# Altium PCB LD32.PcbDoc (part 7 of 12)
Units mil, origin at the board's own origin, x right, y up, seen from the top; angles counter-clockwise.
Board outline 7007.87 x 4368.85 mil, 12 copper layers (Top Layer, Int1 (GND), Int2 (AVDD), Int3 (DVDD), Int4 (GND), Int5 (ST), Int6 (SB), Int8 (AGND), Int7 (AVCC), Int9 (VCCA), Int10 (GND), Bottom Layer), stack 60.136 mil thick; 1165 components, 667 nets, 3910 pads, 2570 vias.
Unrouted connection lines stored in the file: 14.
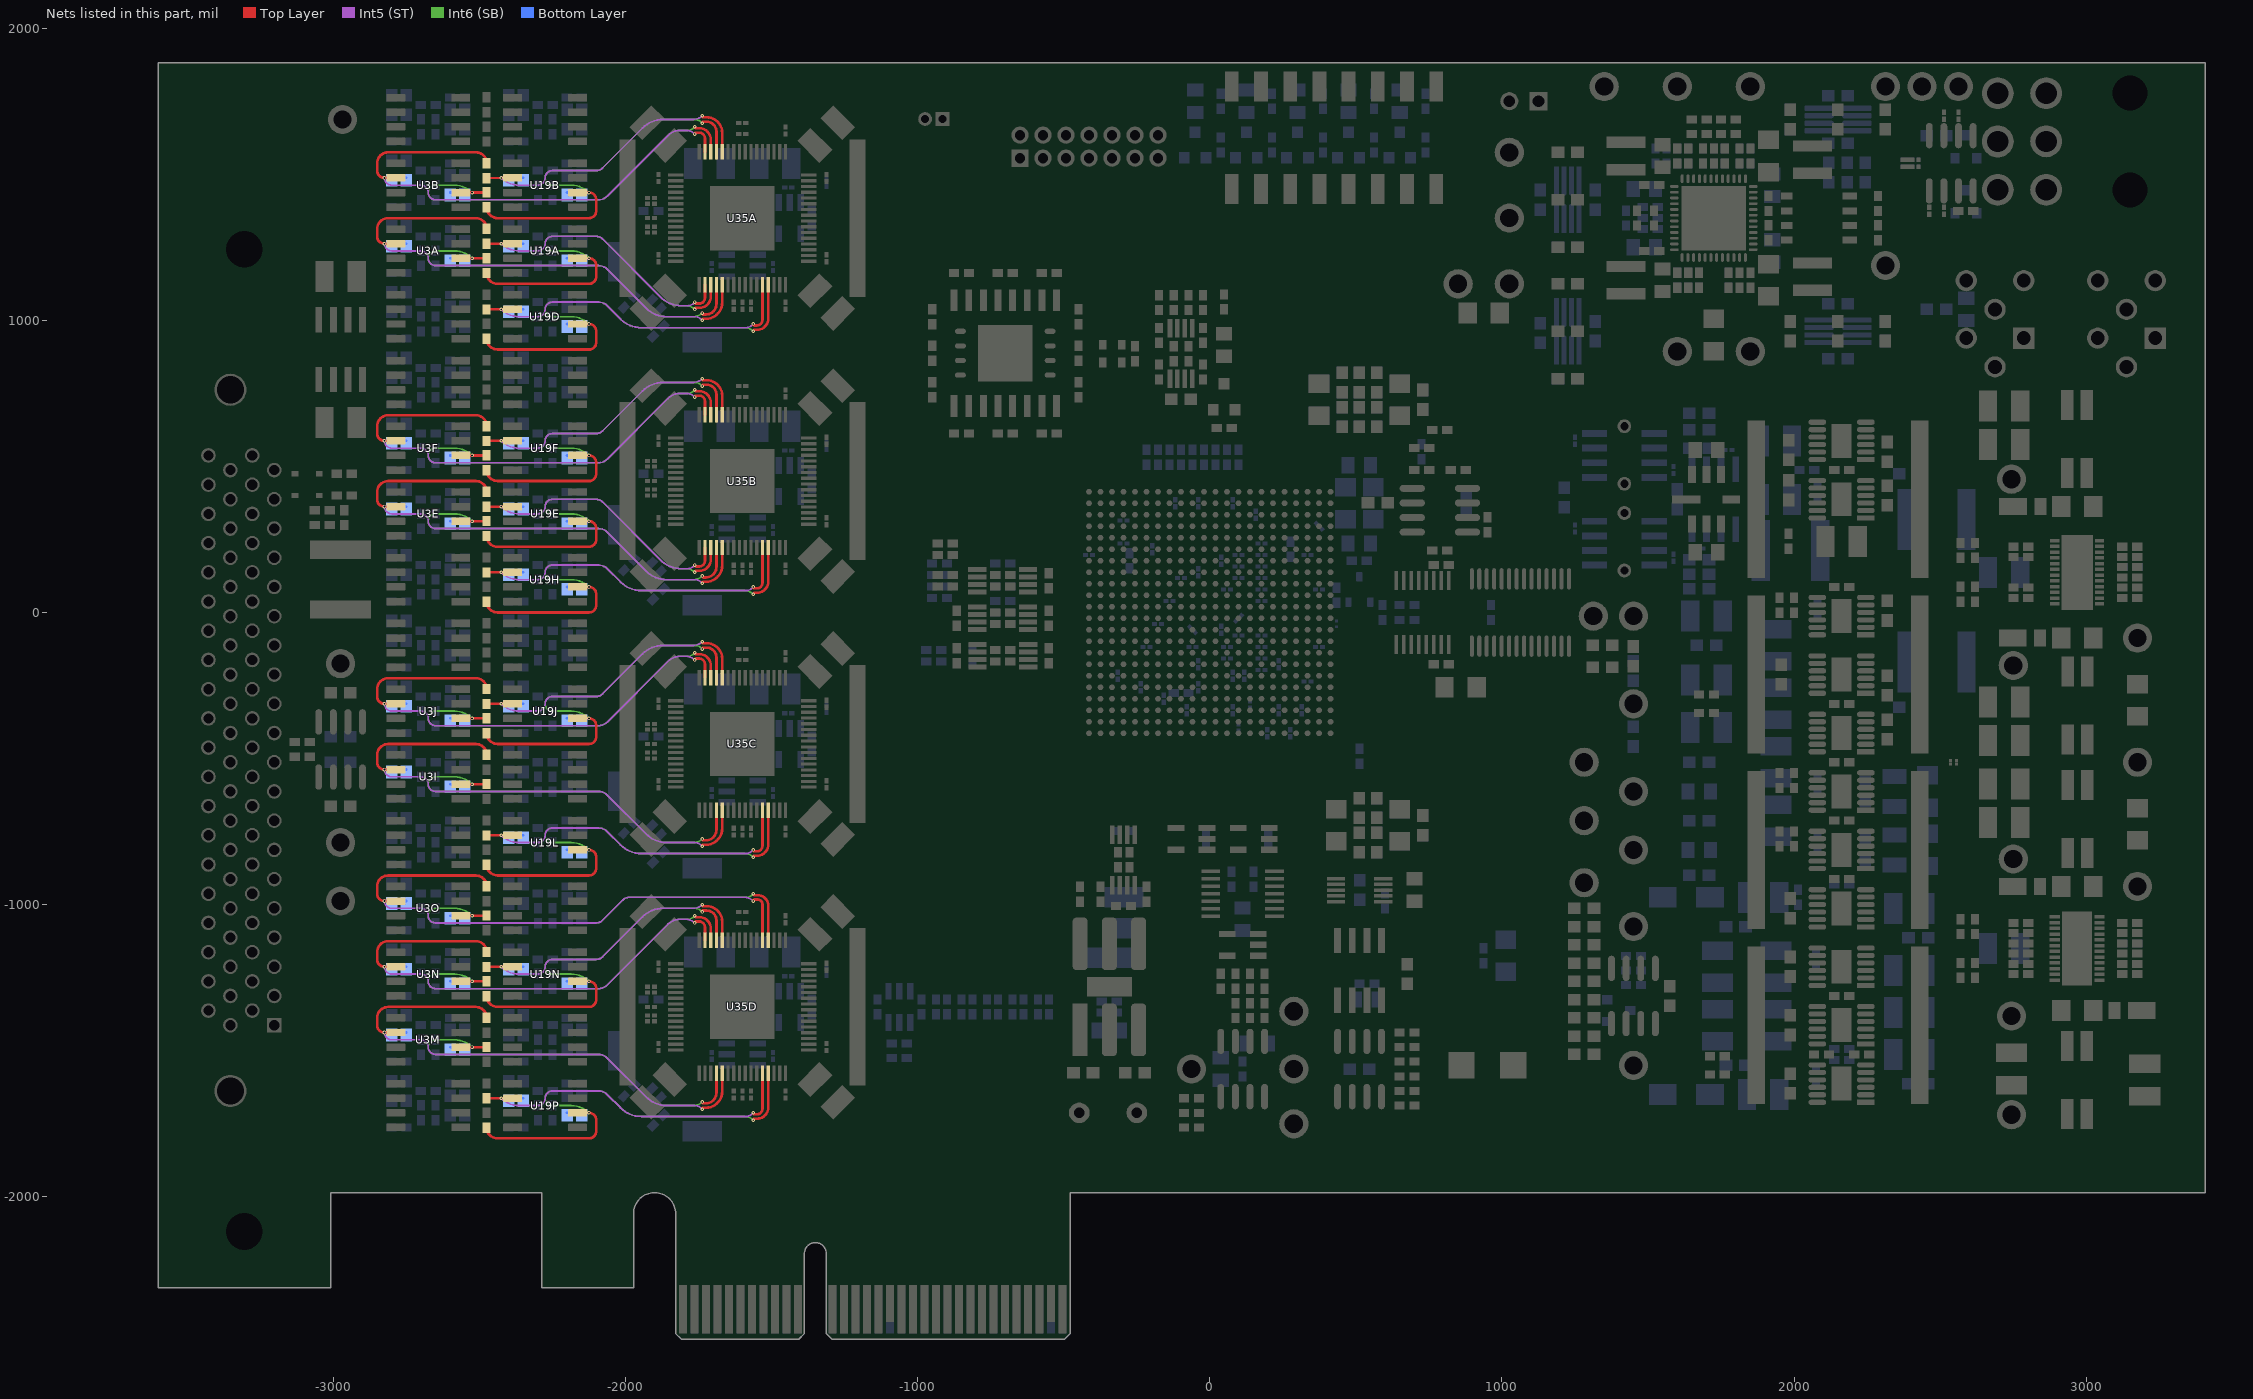
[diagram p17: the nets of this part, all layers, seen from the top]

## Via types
v1: diameter 12, hole 6, Top Layer to Bottom Layer, tented both sides, 1500 vias
v2: diameter 19, hole 10, Top Layer to Bottom Layer, tented both sides, 404 vias
v3: diameter 20, hole 10, Top Layer to Bottom Layer, tented both sides, 337 vias
v4: diameter 14, hole 7, Top Layer to Bottom Layer, tented both sides, 212 vias
v5: diameter 30, hole 15, Top Layer to Bottom Layer, tented both sides, 37 vias
v6: diameter 19.68, hole 7.87, Top Layer to Bottom Layer, 25 vias
v7: diameter 40, hole 20, Top Layer to Bottom Layer, tented both sides, 16 vias
v8: diameter 19.02, hole 10, Top Layer to Bottom Layer, tented both sides, 10 vias
v9: diameter 40, hole 20, Top Layer to Bottom Layer, 9 vias
v10: diameter 60, hole 40, Top Layer to Bottom Layer, 5 vias
v11: diameter 25, hole 13, Top Layer to Bottom Layer, 4 vias
v12: diameter 50, hole 25, Top Layer to Bottom Layer, tented both sides, 4 vias
v13: diameter 35, hole 20, Top Layer to Bottom Layer, 2 vias
v14: diameter 50, hole 25, Top Layer to Bottom Layer, 2 vias
v15: diameter 63, hole 45, Top Layer to Bottom Layer, 1 vias
v16: diameter 14.02, hole 7.01, Top Layer to Bottom Layer, tented both sides, 1 vias
v17: diameter 60, hole 40, Top Layer to Bottom Layer, tented both sides, 1 vias

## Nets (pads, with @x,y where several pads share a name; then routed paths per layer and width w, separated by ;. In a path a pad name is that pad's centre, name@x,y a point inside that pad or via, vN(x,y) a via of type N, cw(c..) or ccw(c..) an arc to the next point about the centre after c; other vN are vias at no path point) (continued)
D3D_N: C399O.2 R7O.1 R399O.1 U3O.6 U35D.4 | length 4442.7
  Top Layer w9: U3O.6@-2563.78,-1037.5 v1(-2525,-1037.5) -2475.59,-1037.5 R7O.1@-2475,-1036.91 ; v1(-1562.5,-962.5) ccw(c-1557.5,-962.5) -1557.5,-967.5 -1547.5,-967.5 cw(c-1547.5,-1003.58) -1511.42,-1003.58 U35D.4@-1511.42,-1122.5
  Int6 (SB) w6: v1(-2525,-1037.5) ccw(c-2585.36,-1097.86) -2585.36,-1012.5 -2650,-1012.5 ccw(c-2650,-1037.5) -2675,-1037.5 ccw(c-2650,-1037.5) -2650,-1062.5 ; v1@-1562.86,-962.25 cw(c-1587.5,-944.82) -1587.5,-975 -1987.5,-975 ccw(c-1987.5,-1005.18) -2008.84,-983.84 -2078.66,-1053.66 cw(c-2100,-1032.32) -2100,-1062.5 ; -2650,-1062.5 -2100,-1062.5 ; -2650,-1062.5 -2100,-1062.5 ; -2650,-1062.5 -2100,-1062.5 ; -2650,-1062.5 -2100,-1062.5 ; -2650,-1062.5 -2100,-1062.5 ; -2650,-1062.5 -2100,-1062.5
  Bottom Layer w9: R399O.1@-2600,-1037.5 v1(-2525,-1037.5)
D3D_P: C463O.2 R8O.1 R447O.1 U3O.2 U35D.5 | length 2887.1
  Top Layer w9: U3O.2@-2786.22,-987.5 v1(-2825,-987.5) cw(c-2825,-962.5) -2850,-962.5 -2850,-937.5 cw(c-2812.5,-937.5) -2812.5,-900 -2511.91,-900 ; v1(-1562.5,-987.5) cw(c-1557.5,-987.5) -1557.5,-982.5 -1547.5,-982.5 cw(c-1547.5,-998.9) -1531.1,-998.9 U35D.5@-1531.1,-1122.5 ; -2511.91,-900 cw(c-2511.91,-936.91) R8O.1@-2475,-936.91 ; -2511.91,-900 cw(c-2511.91,-936.91) R8O.1@-2475,-936.91 ; -2511.91,-900 cw(c-2511.91,-936.91) R8O.1@-2475,-936.91 ; -2511.91,-900 cw(c-2511.91,-936.91) R8O.1@-2475,-936.91 ; -2511.91,-900 cw(c-2511.91,-936.91) R8O.1@-2475,-936.91
  Int5 (ST) w6: v1(-2825,-987.5) ccw(c-2800,-987.5) -2800,-1012.5 -2700,-1012.5 cw(c-2700,-1037.5) -2675,-1037.5 ccw(c-2650,-1037.5) -2650,-1062.5 ; v1(-1562.5,-987.5) ccw(c-1592.68,-1017.68) -1592.5,-975 ; -2650,-1062.5 -2100,-1062.5 ; -2650,-1062.5 -2100,-1062.5 ; -2100,-1062.5 ccw(c-2100,-1032.32) -2078.66,-1053.66 -2008.84,-983.84 cw(c-1987.5,-1005.18) -1987.5,-975 -1592.68,-975 ; -1592.68,-975 cw(c-1592.68,-1017.68) -1592.5,-975 ; -1592.68,-975 -1592.5,-975
  Bottom Layer w9: v1(-2825,-987.5) R447O.1@-2750,-987.5
D4A_N: C319D.2 R7D.2 R335D.1 U19D.6 U35A.45 | length 2545.6
  Top Layer w9: U19D.6@-2163.78,987.5 v1(-2125,987.5) ; v1(-1562.5,962.5) cw(c-1557.5,962.5) -1557.5,967.5 -1550,967.5 ccw(c-1550,1006.08) -1511.42,1006.08 U35A.45@-1511.42,1122.5 ; R7D.2@-2475,936.91 ccw(c-2438.09,936.91) -2438.09,900 ; R7D.2@-2475,936.91 ccw(c-2438.09,936.91) -2438.09,900 ; R7D.2@-2475,936.91 ccw(c-2438.09,936.91) -2438.09,900 ; R7D.2@-2475,936.91 ccw(c-2438.09,936.91) -2438.09,900 ; R7D.2@-2475,936.91 ccw(c-2438.09,936.91) -2438.09,900 ; -2438.09,900 -2125,900 ; -2125,900 ccw(c-2125,925) -2100,925 ; -2125,900 ccw(c-2125,925) -2100,925 ; -2125,900 ccw(c-2125,925) -2100,925 ; -2125,900 ccw(c-2125,925) -2100,925 ; -2125,900 ccw(c-2125,925) -2100,925 ; -2125,900 ccw(c-2125,925) -2100,925 ; -2125,900 ccw(c-2125,925) -2100,925 ; -2125,900 ccw(c-2125,925) -2100,925 ; -2125,900 ccw(c-2125,925) -2100,925 ; -2125,900 ccw(c-2125,925) -2100,925 ; -2125,900 ccw(c-2125,925) -2100,925 ; v1(-2125,987.5) cw(c-2125,962.5) -2100,962.5 ; v1(-2125,987.5) cw(c-2125,962.5) -2100,962.5 ; v1(-2125,987.5) cw(c-2125,962.5) -2100,962.5 ; v1(-2125,987.5) cw(c-2125,962.5) -2100,962.5 ; v1(-2125,987.5) cw(c-2125,962.5) -2100,962.5 ; v1(-2125,987.5) cw(c-2125,962.5) -2100,962.5 ; -2100,925 -2100,962.5
  Int6 (SB) w6: v1(-2125,987.5) ccw(c-2185.36,927.14) -2185.36,1012.5 -2250,1012.5 cw(c-2250,1037.5) -2250,1062.5 -2092.68,1062.5 cw(c-2092.68,1019.82) -2062.5,1050 -2016.79,1004.29 ccw(c-1946.08,1075) -1946.08,975 -1592.68,975 ; v1(-1562.5,962.5) ccw(c-1592.68,932.32) -1592.5,975 ; -1592.68,975 cw(c-1592.68,932.32) -1592.5,975 ; -1592.68,975 -1592.5,975
  Bottom Layer w9: R335D.1@-2200,987.5 v1(-2125,987.5)
D4A_P: C383D.2 R8D.2 R383D.1 U19D.2 U35A.44 | length 1582.5
  Top Layer w9: R8D.2@-2475,1036.91 v1(-2425,1037.5) U19D.2@-2386.22,1037.5 U19D.2@-2380,1037.5 ; v1(-1562.5,987.5) ccw(c-1557.5,987.5) -1557.5,982.5 -1550,982.5 ccw(c-1550,1001.4) -1531.1,1001.4 U35A.44@-1531.1,1122.5
  Int5 (ST) w6: v1(-2425,1037.5) ccw(c-2364.64,1097.86) -2364.64,1012.5 -2300,1012.5 ccw(c-2300,1037.5) -2275,1037.5 cw(c-2250,1037.5) -2250,1062.5 ; v1(-1562.5,987.5) -1566.16,983.84 cw(c-1587.5,1005.18) -1587.5,975 -1946.08,975 cw(c-1946.08,1075) -2016.79,1004.29 -2062.5,1050 ccw(c-2092.68,1019.82) -2092.68,1062.5 ; -2250,1062.5 -2092.68,1062.5 ; -2250,1062.5 -2092.68,1062.5 ; -2250,1062.5 -2092.68,1062.5
  Bottom Layer w9: v1(-2425,1037.5) R383D.1@-2350,1037.5
D4B_N: C319H.2 R7H.2 R335H.1 U19H.6 U35B.45 | length 3370.5
  Top Layer w9: U19H.6@-2163.78,87.5 v1(-2125,87.5) ; -2100,25.08 cw(c-2125.08,25.08) -2125.08,0 -2438.09,0 ; v1(-1562.5,62.5) cw(c-1557.5,62.5) -1557.5,67.5 -1550,67.5 ccw(c-1550,106.08) -1511.42,106.08 U35B.45@-1511.42,222.5 ; R7H.2@-2475,36.91 ccw(c-2438.09,36.91) -2438.09,0 ; R7H.2@-2475,36.91 ccw(c-2438.09,36.91) -2438.09,0 ; R7H.2@-2475,36.91 ccw(c-2438.09,36.91) -2438.09,0 ; R7H.2@-2475,36.91 ccw(c-2438.09,36.91) -2438.09,0 ; R7H.2@-2475,36.91 ccw(c-2438.09,36.91) -2438.09,0 ; -2125,0 ccw(c-2125,25) -2100,25 ; -2125,0 ccw(c-2125,25) -2100,25 ; -2125,0 ccw(c-2125,25) -2100,25 ; -2125,0 ccw(c-2125,25) -2100,25 ; -2125,0 ccw(c-2125,25) -2100,25 ; -2125,0 ccw(c-2125,25) -2100,25 ; -2125,0 ccw(c-2125,25) -2100,25 ; -2125,0 ccw(c-2125,25) -2100,25 ; -2125,0 ccw(c-2125,25) -2100,25 ; -2125,0 ccw(c-2125,25) -2100,25 ; -2125,0 ccw(c-2125,25) -2100,25 ; -2125,0 ccw(c-2125,25) -2100,25 ; -2125,0 ccw(c-2125,25) -2100,25 ; -2125,0 ccw(c-2125,25) -2100,25 ; -2125,0 ccw(c-2125,25) -2100,25 ; -2125,0 ccw(c-2125,25) -2100,25 ; -2125,0 ccw(c-2125,25) -2100,25 ; -2125,0 ccw(c-2125,25) -2100,25 ; -2125,0 ccw(c-2125,25) -2100,25 ; -2125,0 ccw(c-2125,25) -2100,25 ; -2125,0 ccw(c-2125,25) -2100,25 ; v1(-2125,87.5) cw(c-2125,62.5) -2100,62.5 ; v1(-2125,87.5) cw(c-2125,62.5) -2100,62.5 ; v1(-2125,87.5) cw(c-2125,62.5) -2100,62.5 ; v1(-2125,87.5) cw(c-2125,62.5) -2100,62.5 ; v1(-2125,87.5) cw(c-2125,62.5) -2100,62.5 ; v1(-2125,87.5) cw(c-2125,62.5) -2100,62.5 ; v1(-2125,87.5) cw(c-2125,62.5) -2100,62.5 ; v1(-2125,87.5) cw(c-2125,62.5) -2100,62.5 ; v1(-2125,87.5) cw(c-2125,62.5) -2100,62.5 ; v1(-2125,87.5) cw(c-2125,62.5) -2100,62.5 ; v1(-2125,87.5) cw(c-2125,62.5) -2100,62.5 ; v1(-2125,87.5) cw(c-2125,62.5) -2100,62.5 ; -2100,25 -2100,62.5
  Int6 (SB) w6: v1(-2125,87.5) ccw(c-2185.36,27.14) -2185.36,112.5 -2250,112.5 cw(c-2250,137.5) -2250,162.5 ; v1(-1562.5,62.5) ccw(c-1592.68,32.32) -1592.5,75 ; -2250,162.5 -2092.68,162.5 ; -2250,162.5 -2092.68,162.5 ; -2092.68,162.5 cw(c-2092.68,119.82) -2062.5,150 -2016.79,104.29 ccw(c-1946.08,175) -1946.08,75 -1592.68,75 ; -1592.68,75 cw(c-1592.68,32.32) -1592.5,75 ; -1592.68,75 -1592.5,75
  Bottom Layer w9: R335H.1@-2200,87.5 v1(-2125,87.5)
D4B_P: C383H.2 R8H.2 R383H.1 U19H.2 U35B.44 | length 2054.5
  Top Layer w9: R8H.2@-2475,136.91 v1(-2425,137.5) U19H.2@-2386.22,137.5 U19H.2@-2380,137.5 ; v1(-1562.5,87.5) ccw(c-1557.5,87.5) -1557.5,82.5 -1550,82.5 ccw(c-1550,101.4) -1531.1,101.4 U35B.44@-1531.1,222.5
  Int5 (ST) w6: v1(-2425,137.5) ccw(c-2364.64,197.86) -2364.64,112.5 -2300,112.5 ccw(c-2300,137.5) -2275,137.5 cw(c-2250,137.5) -2250,162.5 ; v1(-1562.5,87.5) -1566.16,83.84 cw(c-1587.5,105.18) -1587.5,75 -1946.08,75 cw(c-1946.08,175) -2016.79,104.29 -2062.5,150 ccw(c-2092.68,119.82) -2092.68,162.5 ; -2250,162.5 -2092.68,162.5 ; -2250,162.5 -2092.68,162.5 ; -2250,162.5 -2092.68,162.5 ; -2250,162.5 -2092.68,162.5 ; -2250,162.5 -2092.68,162.5 ; -2250,162.5 -2092.68,162.5
  Bottom Layer w9: v1(-2425,137.5) R383H.1@-2350,137.5
D4C_N: C319L.2 R7L.2 R335L.1 U19L.6 U35C.45 | length 3370.5
  Top Layer w9: U19L.6@-2163.78,-812.5 v1(-2125,-812.5) ; -2100,-874.92 cw(c-2125.08,-874.92) -2125.08,-900 -2438.09,-900 ; v1(-1562.5,-837.5) cw(c-1557.5,-837.5) -1557.5,-832.5 -1550,-832.5 ccw(c-1550,-793.92) -1511.42,-793.92 U35C.45@-1511.42,-677.5 ; R7L.2@-2475,-863.09 ccw(c-2438.09,-863.09) -2438.09,-900 ; R7L.2@-2475,-863.09 ccw(c-2438.09,-863.09) -2438.09,-900 ; R7L.2@-2475,-863.09 ccw(c-2438.09,-863.09) -2438.09,-900 ; R7L.2@-2475,-863.09 ccw(c-2438.09,-863.09) -2438.09,-900 ; R7L.2@-2475,-863.09 ccw(c-2438.09,-863.09) -2438.09,-900 ; -2125,-900 ccw(c-2125,-875) -2100,-875 ; -2125,-900 ccw(c-2125,-875) -2100,-875 ; -2125,-900 ccw(c-2125,-875) -2100,-875 ; -2125,-900 ccw(c-2125,-875) -2100,-875 ; -2125,-900 ccw(c-2125,-875) -2100,-875 ; -2125,-900 ccw(c-2125,-875) -2100,-875 ; -2125,-900 ccw(c-2125,-875) -2100,-875 ; -2125,-900 ccw(c-2125,-875) -2100,-875 ; -2125,-900 ccw(c-2125,-875) -2100,-875 ; -2125,-900 ccw(c-2125,-875) -2100,-875 ; -2125,-900 ccw(c-2125,-875) -2100,-875 ; -2125,-900 ccw(c-2125,-875) -2100,-875 ; -2125,-900 ccw(c-2125,-875) -2100,-875 ; -2125,-900 ccw(c-2125,-875) -2100,-875 ; -2125,-900 ccw(c-2125,-875) -2100,-875 ; -2125,-900 ccw(c-2125,-875) -2100,-875 ; -2125,-900 ccw(c-2125,-875) -2100,-875 ; -2125,-900 ccw(c-2125,-875) -2100,-875 ; -2125,-900 ccw(c-2125,-875) -2100,-875 ; -2125,-900 ccw(c-2125,-875) -2100,-875 ; -2125,-900 ccw(c-2125,-875) -2100,-875 ; v1(-2125,-812.5) cw(c-2125,-837.5) -2100,-837.5 ; v1(-2125,-812.5) cw(c-2125,-837.5) -2100,-837.5 ; v1(-2125,-812.5) cw(c-2125,-837.5) -2100,-837.5 ; v1(-2125,-812.5) cw(c-2125,-837.5) -2100,-837.5 ; v1(-2125,-812.5) cw(c-2125,-837.5) -2100,-837.5 ; v1(-2125,-812.5) cw(c-2125,-837.5) -2100,-837.5 ; v1(-2125,-812.5) cw(c-2125,-837.5) -2100,-837.5 ; v1(-2125,-812.5) cw(c-2125,-837.5) -2100,-837.5 ; v1(-2125,-812.5) cw(c-2125,-837.5) -2100,-837.5 ; v1(-2125,-812.5) cw(c-2125,-837.5) -2100,-837.5 ; v1(-2125,-812.5) cw(c-2125,-837.5) -2100,-837.5 ; v1(-2125,-812.5) cw(c-2125,-837.5) -2100,-837.5 ; -2100,-875 -2100,-837.5
  Int6 (SB) w6: v1(-2125,-812.5) ccw(c-2185.36,-872.86) -2185.36,-787.5 -2250,-787.5 cw(c-2250,-762.5) -2250,-737.5 ; v1(-1562.5,-837.5) ccw(c-1592.68,-867.68) -1592.5,-825 ; -2250,-737.5 -2092.68,-737.5 ; -2250,-737.5 -2092.68,-737.5 ; -2092.68,-737.5 cw(c-2092.68,-780.18) -2062.5,-750 -2016.79,-795.71 ccw(c-1946.08,-725) -1946.08,-825 -1592.68,-825 ; -1592.68,-825 cw(c-1592.68,-867.68) -1592.5,-825 ; -1592.68,-825 -1592.5,-825
  Bottom Layer w9: R335L.1@-2200,-812.5 v1(-2125,-812.5)
D4C_P: C383L.2 R8L.2 R383L.1 U19L.2 U35C.44 | length 2054.5
  Top Layer w9: R8L.2@-2475,-763.09 v1(-2425,-762.5) U19L.2@-2386.22,-762.5 U19L.2@-2380,-762.5 ; v1(-1562.5,-812.5) ccw(c-1557.5,-812.5) -1557.5,-817.5 -1550,-817.5 ccw(c-1550,-798.6) -1531.1,-798.6 U35C.44@-1531.1,-677.5
  Int5 (ST) w6: v1(-2425,-762.5) ccw(c-2364.64,-702.14) -2364.64,-787.5 -2300,-787.5 ccw(c-2300,-762.5) -2275,-762.5 cw(c-2250,-762.5) -2250,-737.5 ; v1(-1562.5,-812.5) -1566.16,-816.16 cw(c-1587.5,-794.82) -1587.5,-825 -1946.08,-825 cw(c-1946.08,-725) -2016.79,-795.71 -2062.5,-750 ccw(c-2092.68,-780.18) -2092.68,-737.5 ; -2250,-737.5 -2092.68,-737.5 ; -2250,-737.5 -2092.68,-737.5 ; -2250,-737.5 -2092.68,-737.5 ; -2250,-737.5 -2092.68,-737.5 ; -2250,-737.5 -2092.68,-737.5 ; -2250,-737.5 -2092.68,-737.5
  Bottom Layer w9: v1(-2425,-762.5) R383L.1@-2350,-762.5
D4D_N: C319P.2 R7P.2 R335P.1 U19P.6 U35D.45 | length 2549.5
  Top Layer w9: R7P.2@-2475,-1763.09 ccw(c-2438.09,-1763.09) -2438.09,-1800 -2125,-1800 ; U19P.6@-2163.78,-1712.5 v1(-2125,-1712.5) ; v1(-1562.5,-1737.5) cw(c-1557.5,-1737.5) -1557.5,-1732.5 -1550,-1732.5 ccw(c-1550,-1693.92) -1511.42,-1693.92 U35D.45@-1511.42,-1577.5 ; -2125,-1800 ccw(c-2125,-1775) -2100,-1775 ; -2125,-1800 ccw(c-2125,-1775) -2100,-1775 ; -2125,-1800 ccw(c-2125,-1775) -2100,-1775 ; -2125,-1800 ccw(c-2125,-1775) -2100,-1775 ; -2125,-1800 ccw(c-2125,-1775) -2100,-1775 ; -2125,-1800 ccw(c-2125,-1775) -2100,-1775 ; -2125,-1800 ccw(c-2125,-1775) -2100,-1775 ; -2125,-1800 ccw(c-2125,-1775) -2100,-1775 ; -2125,-1800 ccw(c-2125,-1775) -2100,-1775 ; -2125,-1800 ccw(c-2125,-1775) -2100,-1775 ; -2125,-1800 ccw(c-2125,-1775) -2100,-1775 ; -2125,-1800 ccw(c-2125,-1775) -2100,-1775 ; v1(-2125,-1712.5) cw(c-2125,-1737.5) -2100,-1737.5 ; v1(-2125,-1712.5) cw(c-2125,-1737.5) -2100,-1737.5 ; v1(-2125,-1712.5) cw(c-2125,-1737.5) -2100,-1737.5 ; v1(-2125,-1712.5) cw(c-2125,-1737.5) -2100,-1737.5 ; v1(-2125,-1712.5) cw(c-2125,-1737.5) -2100,-1737.5 ; v1(-2125,-1712.5) cw(c-2125,-1737.5) -2100,-1737.5 ; v1(-2125,-1712.5) cw(c-2125,-1737.5) -2100,-1737.5 ; -2100,-1775 -2100,-1737.5
  Int6 (SB) w6: v1(-2125,-1712.5) ccw(c-2185.36,-1772.86) -2185.36,-1687.5 -2250,-1687.5 cw(c-2250,-1662.5) -2275,-1662.5 cw(c-2250,-1662.5) -2250,-1637.5 ; v1(-1562.5,-1737.5) ccw(c-1592.68,-1767.68) -1592.5,-1725 ; -2250,-1637.5 -2092.68,-1637.5 ; -2250,-1637.5 -2092.68,-1637.5 ; -2092.68,-1637.5 cw(c-2092.68,-1680.18) -2062.5,-1650 -2016.79,-1695.71 ccw(c-1946.08,-1625) -1946.08,-1725 -1592.68,-1725 ; -1592.68,-1725 cw(c-1592.68,-1767.68) -1592.5,-1725 ; -1592.68,-1725 -1592.5,-1725
  Bottom Layer w9: R335P.1@-2200,-1712.5 v1(-2125,-1712.5)
D4D_P: C383P.2 R8P.2 R383P.1 U19P.2 U35D.44 | length 1739.8
  Top Layer w9: R8P.2@-2475,-1663.09 v1(-2425,-1662.5) U19P.2@-2386.22,-1662.5 U19P.2@-2380,-1662.5 ; v1(-1562.5,-1712.5) ccw(c-1557.5,-1712.5) -1557.5,-1717.5 -1550,-1717.5 ccw(c-1550,-1698.6) -1531.1,-1698.6 U35D.44@-1531.1,-1577.5
  Int5 (ST) w6: v1(-2425,-1662.5) ccw(c-2364.64,-1602.14) -2364.64,-1687.5 -2300,-1687.5 ccw(c-2300,-1662.5) -2275,-1662.5 cw(c-2250,-1662.5) -2250,-1637.5 ; v1(-1562.5,-1712.5) -1566.16,-1716.16 cw(c-1587.5,-1694.82) -1587.5,-1725 -1946.08,-1725 cw(c-1946.08,-1625) -2016.79,-1695.71 -2062.5,-1650 ccw(c-2092.68,-1680.18) -2092.68,-1637.5 ; -2250,-1637.5 -2092.68,-1637.5 ; -2250,-1637.5 -2092.68,-1637.5 ; -2250,-1637.5 -2092.68,-1637.5 ; -2250,-1637.5 -2092.68,-1637.5
  Bottom Layer w9: v1(-2425,-1662.5) R383P.1@-2350,-1662.5
D5A_N: C319B.2 R7B.2 R335B.1 U19B.6 U35A.13 | length 2349.7
  Top Layer w9: U19B.6@-2163.78,1437.5 v1(-2125,1437.5) ; -2125.08,1349.86 -2438.09,1349.86 -2438.09,1350 ; v1@-1735,1680 -1722.5,1680 cw(c-1722.5,1646.08) -1688.58,1646.08 U35A.13@-1688.58,1577.5 ; R7B.2@-2475,1386.91 ccw(c-2438.09,1386.91) -2438.09,1350 ; R7B.2@-2475,1386.91 ccw(c-2438.09,1386.91) -2438.09,1350 ; R7B.2@-2475,1386.91 ccw(c-2438.09,1386.91) -2438.09,1350 ; R7B.2@-2475,1386.91 ccw(c-2438.09,1386.91) -2438.09,1350 ; R7B.2@-2475,1386.91 ccw(c-2438.09,1386.91) -2438.09,1350 ; -2125,1350 ccw(c-2125,1375) -2100,1375 ; -2125,1350 ccw(c-2125,1375) -2100,1375 ; -2125,1350 ccw(c-2125,1375) -2100,1375 ; -2125,1350 ccw(c-2125,1375) -2100,1375 ; -2125,1350 ccw(c-2125,1375) -2100,1375 ; -2125,1350 ccw(c-2125,1375) -2100,1375 ; -2125,1350 ccw(c-2125,1375) -2100,1375 ; -2125,1350 ccw(c-2125,1375) -2100,1375 ; -2125,1350 ccw(c-2125,1375) -2100,1375 ; -2125,1350 ccw(c-2125,1375) -2100,1375 ; -2125,1350 ccw(c-2125,1375) -2100,1375 ; v1(-2125,1437.5) cw(c-2125,1412.5) -2100,1412.5 ; v1(-2125,1437.5) cw(c-2125,1412.5) -2100,1412.5 ; v1(-2125,1437.5) cw(c-2125,1412.5) -2100,1412.5 ; v1(-2125,1437.5) cw(c-2125,1412.5) -2100,1412.5 ; v1(-2125,1437.5) cw(c-2125,1412.5) -2100,1412.5 ; v1(-2125,1437.5) cw(c-2125,1412.5) -2100,1412.5 ; -2100,1375 -2100,1412.5
  Int6 (SB) w6: v1(-2125,1437.5) ccw(c-2185.36,1377.14) -2185.36,1462.5 -2250,1462.5 cw(c-2250,1487.5) -2275,1487.5 cw(c-2250,1487.5) -2250,1512.5 -2100,1512.5 ccw(c-2100,1542.68) -2078.66,1521.34 -1941.79,1658.21 cw(c-1871.08,1587.5) -1871.08,1687.5 -1762.5,1687.5 cw(c-1762.5,1657.32) v1@-1737.86,1674.75
  Bottom Layer w9: R335B.1@-2200,1437.5 v1(-2125,1437.5)
  other v1: -1737.5,1675
D5A_P: C383B.2 R8B.2 R383B.1 U19B.2 U35A.12 | length 1423.7
  Top Layer w9: R8B.2@-2475,1486.91 v1(-2425,1487.5) U19B.2@-2386.22,1487.5 U19B.2@-2380,1487.5 ; v1@-1735,1695 -1722.5,1695 cw(c-1722.5,1641.4) -1668.9,1641.4 U35A.12@-1668.9,1577.5
  Int5 (ST) w6: v1(-2425,1487.5) ccw(c-2364.64,1547.86) -2364.64,1462.5 -2300,1462.5 ccw(c-2300,1487.5) -2275,1487.5 cw(c-2250,1487.5) -2250,1512.5 ; v1(-1737.5,1700) cw(c-1767.68,1730.18) -1767.5,1687.5 ; -2250,1512.5 -2100,1512.5 ; -2250,1512.5 -2100,1512.5 ; -2250,1512.5 -2100,1512.5 ; -2100,1512.5 ccw(c-2100,1542.68) -2078.66,1521.34 -1941.79,1658.21 cw(c-1871.08,1587.5) -1871.08,1687.5 -1862.5,1687.5 -1767.68,1687.5 ; -1767.68,1687.5 ccw(c-1767.68,1730.18) -1767.5,1687.5 ; -1767.68,1687.5 -1767.5,1687.5
  Bottom Layer w9: v1(-2425,1487.5) R383B.1@-2350,1487.5
D5B_N: C319F.2 R7F.2 R335F.1 U19F.6 U35B.13 | length 3167.3
  Top Layer w9: U19F.6@-2163.78,537.5 v1(-2125,537.5) ; -2100,475.08 cw(c-2125.08,475.08) -2125.08,450 -2438.09,450 ; v1@-1735,780 -1722.5,780 cw(c-1722.5,746.08) -1688.58,746.08 U35B.13@-1688.58,677.5 ; R7F.2@-2475,486.91 ccw(c-2438.09,486.91) -2438.09,450 ; R7F.2@-2475,486.91 ccw(c-2438.09,486.91) -2438.09,450 ; R7F.2@-2475,486.91 ccw(c-2438.09,486.91) -2438.09,450 ; R7F.2@-2475,486.91 ccw(c-2438.09,486.91) -2438.09,450 ; R7F.2@-2475,486.91 ccw(c-2438.09,486.91) -2438.09,450 ; -2125,450 ccw(c-2125,475) -2100,475 ; -2125,450 ccw(c-2125,475) -2100,475 ; -2125,450 ccw(c-2125,475) -2100,475 ; -2125,450 ccw(c-2125,475) -2100,475 ; -2125,450 ccw(c-2125,475) -2100,475 ; -2125,450 ccw(c-2125,475) -2100,475 ; -2125,450 ccw(c-2125,475) -2100,475 ; -2125,450 ccw(c-2125,475) -2100,475 ; -2125,450 ccw(c-2125,475) -2100,475 ; -2125,450 ccw(c-2125,475) -2100,475 ; -2125,450 ccw(c-2125,475) -2100,475 ; -2125,450 ccw(c-2125,475) -2100,475 ; -2125,450 ccw(c-2125,475) -2100,475 ; -2125,450 ccw(c-2125,475) -2100,475 ; -2125,450 ccw(c-2125,475) -2100,475 ; -2125,450 ccw(c-2125,475) -2100,475 ; -2125,450 ccw(c-2125,475) -2100,475 ; -2125,450 ccw(c-2125,475) -2100,475 ; -2125,450 ccw(c-2125,475) -2100,475 ; -2125,450 ccw(c-2125,475) -2100,475 ; -2125,450 ccw(c-2125,475) -2100,475 ; v1(-2125,537.5) cw(c-2125,512.5) -2100,512.5 ; v1(-2125,537.5) cw(c-2125,512.5) -2100,512.5 ; v1(-2125,537.5) cw(c-2125,512.5) -2100,512.5 ; v1(-2125,537.5) cw(c-2125,512.5) -2100,512.5 ; v1(-2125,537.5) cw(c-2125,512.5) -2100,512.5 ; v1(-2125,537.5) cw(c-2125,512.5) -2100,512.5 ; v1(-2125,537.5) cw(c-2125,512.5) -2100,512.5 ; v1(-2125,537.5) cw(c-2125,512.5) -2100,512.5 ; v1(-2125,537.5) cw(c-2125,512.5) -2100,512.5 ; v1(-2125,537.5) cw(c-2125,512.5) -2100,512.5 ; v1(-2125,537.5) cw(c-2125,512.5) -2100,512.5 ; v1(-2125,537.5) cw(c-2125,512.5) -2100,512.5 ; -2100,475 -2100,512.5
  Int6 (SB) w6: v1(-2125,537.5) ccw(c-2185.36,477.14) -2185.36,562.5 -2250,562.5 cw(c-2250,587.5) -2275,587.5 cw(c-2250,587.5) -2250,612.5 ; v1@-1737.86,774.75 ccw(c-1762.5,757.32) -1762.5,787.5 -1871.08,787.5 ccw(c-1871.08,687.5) -1941.79,758.21 -2078.66,621.34 cw(c-2100,642.68) -2100,612.5 ; -2250,612.5 -2100,612.5 ; -2250,612.5 -2100,612.5
  Bottom Layer w9: R335F.1@-2200,537.5 v1(-2125,537.5)
  other v1: -1737.5,775
D5B_P: C383F.2 R8F.2 R383F.1 U19F.2 U35B.12 | length 1873.7
  Top Layer w9: R8F.2@-2475,586.91 v1(-2425,587.5) U19F.2@-2386.22,587.5 U19F.2@-2380,587.5 ; v1@-1735,795 -1722.5,795 cw(c-1722.5,741.4) -1668.9,741.4 U35B.12@-1668.9,677.5
  Int5 (ST) w6: v1(-2425,587.5) ccw(c-2364.64,647.86) -2364.64,562.5 -2300,562.5 ccw(c-2300,587.5) -2275,587.5 cw(c-2250,587.5) -2250,612.5 ; v1(-1737.5,800) cw(c-1767.68,830.18) -1767.5,787.5 ; -2250,612.5 -2100,612.5 ; -2250,612.5 -2100,612.5 ; -2250,612.5 -2100,612.5 ; -2250,612.5 -2100,612.5 ; -2250,612.5 -2100,612.5 ; -2250,612.5 -2100,612.5 ; -2100,612.5 ccw(c-2100,642.68) -2078.66,621.34 -1941.79,758.21 cw(c-1871.08,687.5) -1871.08,787.5 -1862.5,787.5 -1767.68,787.5 ; -1767.68,787.5 ccw(c-1767.68,830.18) -1767.5,787.5 ; -1767.68,787.5 -1767.5,787.5
  Bottom Layer w9: v1(-2425,587.5) R383F.1@-2350,587.5
D5C_N: C319J.2 R7J.2 R335J.1 U19J.6 U35C.13 | length 3167.3
  Top Layer w9: U19J.6@-2163.78,-362.5 v1(-2125,-362.5) ; -2100,-425.12 cw(c-2125,-425.12) -2125,-450.12 -2438.09,-450.12 -2438.09,-450 ; v1@-1735,-120 -1722.5,-120 cw(c-1722.5,-153.92) -1688.58,-153.92 U35C.13@-1688.58,-222.5 ; R7J.2@-2475,-413.09 ccw(c-2438.09,-413.09) -2438.09,-450 ; R7J.2@-2475,-413.09 ccw(c-2438.09,-413.09) -2438.09,-450 ; R7J.2@-2475,-413.09 ccw(c-2438.09,-413.09) -2438.09,-450 ; R7J.2@-2475,-413.09 ccw(c-2438.09,-413.09) -2438.09,-450 ; R7J.2@-2475,-413.09 ccw(c-2438.09,-413.09) -2438.09,-450 ; -2125,-450 ccw(c-2125,-425) -2100,-425 ; -2125,-450 ccw(c-2125,-425) -2100,-425 ; -2125,-450 ccw(c-2125,-425) -2100,-425 ; -2125,-450 ccw(c-2125,-425) -2100,-425 ; -2125,-450 ccw(c-2125,-425) -2100,-425 ; -2125,-450 ccw(c-2125,-425) -2100,-425 ; -2125,-450 ccw(c-2125,-425) -2100,-425 ; -2125,-450 ccw(c-2125,-425) -2100,-425 ; -2125,-450 ccw(c-2125,-425) -2100,-425 ; -2125,-450 ccw(c-2125,-425) -2100,-425 ; -2125,-450 ccw(c-2125,-425) -2100,-425 ; -2125,-450 ccw(c-2125,-425) -2100,-425 ; -2125,-450 ccw(c-2125,-425) -2100,-425 ; -2125,-450 ccw(c-2125,-425) -2100,-425 ; -2125,-450 ccw(c-2125,-425) -2100,-425 ; -2125,-450 ccw(c-2125,-425) -2100,-425 ; -2125,-450 ccw(c-2125,-425) -2100,-425 ; -2125,-450 ccw(c-2125,-425) -2100,-425 ; -2125,-450 ccw(c-2125,-425) -2100,-425 ; -2125,-450 ccw(c-2125,-425) -2100,-425 ; -2125,-450 ccw(c-2125,-425) -2100,-425 ; v1(-2125,-362.5) cw(c-2125,-387.5) -2100,-387.5 ; v1(-2125,-362.5) cw(c-2125,-387.5) -2100,-387.5 ; v1(-2125,-362.5) cw(c-2125,-387.5) -2100,-387.5 ; v1(-2125,-362.5) cw(c-2125,-387.5) -2100,-387.5 ; v1(-2125,-362.5) cw(c-2125,-387.5) -2100,-387.5 ; v1(-2125,-362.5) cw(c-2125,-387.5) -2100,-387.5 ; v1(-2125,-362.5) cw(c-2125,-387.5) -2100,-387.5 ; v1(-2125,-362.5) cw(c-2125,-387.5) -2100,-387.5 ; v1(-2125,-362.5) cw(c-2125,-387.5) -2100,-387.5 ; v1(-2125,-362.5) cw(c-2125,-387.5) -2100,-387.5 ; v1(-2125,-362.5) cw(c-2125,-387.5) -2100,-387.5 ; v1(-2125,-362.5) cw(c-2125,-387.5) -2100,-387.5 ; -2100,-425 -2100,-387.5
  Int6 (SB) w6: v1(-2125,-362.5) ccw(c-2185.36,-422.86) -2185.36,-337.5 -2250,-337.5 cw(c-2250,-312.5) -2275,-312.5 cw(c-2250,-312.5) -2250,-287.5 ; v1@-1737.86,-125.25 ccw(c-1762.5,-142.68) -1762.5,-112.5 -1871.08,-112.5 ccw(c-1871.08,-212.5) -1941.79,-141.79 -2078.66,-278.66 cw(c-2100,-257.32) -2100,-287.5 ; -2250,-287.5 -2100,-287.5 ; -2250,-287.5 -2100,-287.5
  Bottom Layer w9: R335J.1@-2200,-362.5 v1(-2125,-362.5)
  other v1: -1737.5,-125
D5C_P: C383J.2 R8J.2 R383J.1 U19J.2 U35C.12 | length 1873.7
  Top Layer w9: R8J.2@-2475,-313.09 v1(-2425,-312.5) U19J.2@-2386.22,-312.5 U19J.2@-2380,-312.5 ; v1@-1735,-105 -1722.5,-105 cw(c-1722.5,-158.6) -1668.9,-158.6 U35C.12@-1668.9,-222.5
  Int5 (ST) w6: v1(-2425,-312.5) ccw(c-2364.64,-252.14) -2364.64,-337.5 -2300,-337.5 ccw(c-2300,-312.5) -2275,-312.5 cw(c-2250,-312.5) -2250,-287.5 ; v1(-1737.5,-100) cw(c-1767.68,-69.82) -1767.5,-112.5 ; -2250,-287.5 -2100,-287.5 ; -2250,-287.5 -2100,-287.5 ; -2250,-287.5 -2100,-287.5 ; -2250,-287.5 -2100,-287.5 ; -2250,-287.5 -2100,-287.5 ; -2250,-287.5 -2100,-287.5 ; -2100,-287.5 ccw(c-2100,-257.32) -2078.66,-278.66 -1941.79,-141.79 cw(c-1871.08,-212.5) -1871.08,-112.5 -1862.5,-112.5 -1767.68,-112.5 ; -1767.68,-112.5 ccw(c-1767.68,-69.82) -1767.5,-112.5 ; -1767.68,-112.5 -1767.5,-112.5
  Bottom Layer w9: v1(-2425,-312.5) R383J.1@-2350,-312.5
D5D_N: C319N.2 R7N.2 R335N.1 U19N.6 U35D.13 | length 2578.2
  Top Layer w9: U19N.6@-2163.78,-1262.5 v1(-2125,-1262.5) ; v1@-1735,-1020 -1722.5,-1020 cw(c-1722.5,-1053.92) -1688.58,-1053.92 U35D.13@-1688.58,-1122.5 ; R7N.2@-2475,-1313.09 ccw(c-2438.09,-1313.09) -2438.09,-1350 ; R7N.2@-2475,-1313.09 ccw(c-2438.09,-1313.09) -2438.09,-1350 ; R7N.2@-2475,-1313.09 ccw(c-2438.09,-1313.09) -2438.09,-1350 ; R7N.2@-2475,-1313.09 ccw(c-2438.09,-1313.09) -2438.09,-1350 ; R7N.2@-2475,-1313.09 ccw(c-2438.09,-1313.09) -2438.09,-1350 ; -2438.09,-1350 -2125,-1350 ; -2125,-1350 ccw(c-2125,-1325) -2100,-1325 ; -2125,-1350 ccw(c-2125,-1325) -2100,-1325 ; -2125,-1350 ccw(c-2125,-1325) -2100,-1325 ; -2125,-1350 ccw(c-2125,-1325) -2100,-1325 ; -2125,-1350 ccw(c-2125,-1325) -2100,-1325 ; -2125,-1350 ccw(c-2125,-1325) -2100,-1325 ; -2125,-1350 ccw(c-2125,-1325) -2100,-1325 ; -2125,-1350 ccw(c-2125,-1325) -2100,-1325 ; -2125,-1350 ccw(c-2125,-1325) -2100,-1325 ; -2125,-1350 ccw(c-2125,-1325) -2100,-1325 ; -2125,-1350 ccw(c-2125,-1325) -2100,-1325 ; -2125,-1350 ccw(c-2125,-1325) -2100,-1325 ; v1(-2125,-1262.5) cw(c-2125,-1287.5) -2100,-1287.5 ; v1(-2125,-1262.5) cw(c-2125,-1287.5) -2100,-1287.5 ; v1(-2125,-1262.5) cw(c-2125,-1287.5) -2100,-1287.5 ; v1(-2125,-1262.5) cw(c-2125,-1287.5) -2100,-1287.5 ; v1(-2125,-1262.5) cw(c-2125,-1287.5) -2100,-1287.5 ; v1(-2125,-1262.5) cw(c-2125,-1287.5) -2100,-1287.5 ; v1(-2125,-1262.5) cw(c-2125,-1287.5) -2100,-1287.5 ; -2100,-1325 -2100,-1287.5
  Int6 (SB) w6: v1(-2125,-1262.5) ccw(c-2185.36,-1322.86) -2185.36,-1237.5 -2250,-1237.5 cw(c-2250,-1212.5) -2275,-1212.5 cw(c-2250,-1212.5) -2250,-1187.5 ; v1@-1737.86,-1025.25 ccw(c-1762.5,-1042.68) -1762.5,-1012.5 -1871.08,-1012.5 ccw(c-1871.08,-1112.5) -1941.79,-1041.79 -2078.66,-1178.66 cw(c-2100,-1157.32) -2100,-1187.5 ; -2250,-1187.5 -2100,-1187.5 ; -2250,-1187.5 -2100,-1187.5
  Bottom Layer w9: R335N.1@-2200,-1262.5 v1(-2125,-1262.5)
  other v1: -1737.5,-1025
D5D_P: C383N.2 R8N.2 R383N.1 U19N.2 U35D.12 | length 1573.7
  Top Layer w9: R8N.2@-2475,-1213.09 v1(-2425,-1212.5) U19N.2@-2386.22,-1212.5 U19N.2@-2380,-1212.5 ; v1@-1735,-1005 -1722.5,-1005 cw(c-1722.5,-1058.6) -1668.9,-1058.6 U35D.12@-1668.9,-1122.5
  Int5 (ST) w6: v1(-2425,-1212.5) ccw(c-2364.64,-1152.14) -2364.64,-1237.5 -2300,-1237.5 ccw(c-2300,-1212.5) -2275,-1212.5 cw(c-2250,-1212.5) -2250,-1187.5 ; v1(-1737.5,-1000) cw(c-1767.68,-969.82) -1767.5,-1012.5 ; -2250,-1187.5 -2100,-1187.5 ; -2250,-1187.5 -2100,-1187.5 ; -2250,-1187.5 -2100,-1187.5 ; -2250,-1187.5 -2100,-1187.5 ; -2100,-1187.5 ccw(c-2100,-1157.32) -2078.66,-1178.66 -1941.79,-1041.79 cw(c-1871.08,-1112.5) -1871.08,-1012.5 -1862.5,-1012.5 -1767.68,-1012.5 ; -1767.68,-1012.5 ccw(c-1767.68,-969.82) -1767.5,-1012.5 ; -1767.68,-1012.5 -1767.5,-1012.5
  Bottom Layer w9: v1(-2425,-1212.5) R383N.1@-2350,-1212.5
D6A_N: C399A.2 R7A.1 R399A.1 U3A.6 U35A.36 | length 2052.6
  Top Layer w9: U3A.6@-2563.78,1212.5 v1(-2525,1212.5) -2475.59,1212.5 R7A.1@-2475,1213.09 ; v1(-1737.5,1025) ccw(c-1732.5,1025) -1732.5,1020 -1725,1020 ccw(c-1725,1056.42) -1688.58,1056.42 U35A.36@-1688.58,1122.5
  Int6 (SB) w6: v1(-2525,1212.5) ccw(c-2585.36,1152.14) -2585.36,1237.5 -2650,1237.5 ccw(c-2650,1212.5) -2650,1187.5 ; v1(-1737.5,1025) cw(c-1767.68,1055.18) -1767.5,1012.5 ; -2650,1187.5 -2092.68,1187.5 ; -2650,1187.5 -2092.68,1187.5 ; -2092.68,1187.5 cw(c-2092.68,1144.82) -2062.5,1175 -1929.29,1041.79 ccw(c-1858.58,1112.5) -1858.58,1012.5 -1767.68,1012.5 ; -1767.68,1012.5 ccw(c-1767.68,1055.18) -1767.5,1012.5 ; -1767.68,1012.5 -1767.5,1012.5
  Bottom Layer w9: R399A.1@-2600,1212.5 v1(-2525,1212.5)
D6A_P: C463A.2 R8A.1 R447A.1 U3A.2 U35A.37 | length 2192.8
  Top Layer w9: U3A.2@-2786.22,1262.5 v1(-2825,1262.5) cw(c-2825,1287.5) -2850,1287.5 -2850,1312.5 cw(c-2812.5,1312.5) -2812.5,1350 -2511.91,1350 ; v1(-1737.5,1000) cw(c-1732.5,1000) -1732.5,1005 -1725,1005 ccw(c-1725,1061.1) -1668.9,1061.1 U35A.37@-1668.9,1122.5 ; -2511.91,1350 cw(c-2511.91,1313.09) R8A.1@-2475,1313.09 ; -2511.91,1350 cw(c-2511.91,1313.09) R8A.1@-2475,1313.09 ; -2511.91,1350 cw(c-2511.91,1313.09) R8A.1@-2475,1313.09 ; -2511.91,1350 cw(c-2511.91,1313.09) R8A.1@-2475,1313.09 ; -2511.91,1350 cw(c-2511.91,1313.09) R8A.1@-2475,1313.09
  Int5 (ST) w6: v1(-2825,1262.5) ccw(c-2800,1262.5) -2800,1237.5 -2700,1237.5 cw(c-2700,1212.5) -2675,1212.5 ccw(c-2650,1212.5) -2650,1187.5 -2092.68,1187.5 cw(c-2092.68,1144.82) -2062.5,1175 -1929.29,1041.79 ccw(c-1858.58,1112.5) -1858.58,1012.5 -1762.5,1012.5 cw(c-1762.5,982.32) -1741.16,1003.66 v1(-1737.5,1000)
  Bottom Layer w9: v1(-2825,1262.5) R447A.1@-2750,1262.5
D6B_N: C399E.2 R7E.1 R399E.1 U3E.6 U35B.36 | length 3167.2
  Top Layer w9: U3E.6@-2563.78,312.5 v1(-2525,312.5) -2475.59,312.5 R7E.1@-2475,313.09 ; v1(-1737.5,125) ccw(c-1732.5,125) -1732.5,120 -1725,120 ccw(c-1725,156.42) -1688.58,156.42 U35B.36@-1688.58,222.5
  Int6 (SB) w6: v1(-2525,312.5) ccw(c-2585.36,252.14) -2585.36,337.5 -2650,337.5 ccw(c-2650,312.5) -2650,287.5 ; v1(-1737.5,125) cw(c-1767.68,155.18) -1767.5,112.5 ; -2650,287.5 -2092.68,287.5 ; -2650,287.5 -2092.68,287.5 ; -2650,287.5 -2092.68,287.5 ; -2650,287.5 -2092.68,287.5 ; -2092.68,287.5 cw(c-2092.68,244.82) -2062.5,275 -1929.29,141.79 ccw(c-1858.58,212.5) -1858.58,112.5 -1767.68,112.5 ; -1767.68,112.5 ccw(c-1767.68,155.18) -1767.5,112.5 ; -1767.68,112.5 -1767.5,112.5
  Bottom Layer w9: R399E.1@-2600,312.5 v1(-2525,312.5)
D6B_P: C463E.2 R8E.1 R447E.1 U3E.2 U35B.37 | length 2750.2
  Top Layer w9: U3E.2@-2786.22,362.5 v1(-2825,362.5) cw(c-2825,387.5) -2850,387.5 -2850,412.5 cw(c-2812.5,412.5) -2812.5,450 -2511.91,450 ; v1(-1737.5,100) cw(c-1732.5,100) -1732.5,105 -1725,105 ccw(c-1725,161.1) -1668.9,161.1 U35B.37@-1668.9,222.5 ; -2511.91,450 cw(c-2511.91,413.09) R8E.1@-2475,413.09 ; -2511.91,450 cw(c-2511.91,413.09) R8E.1@-2475,413.09 ; -2511.91,450 cw(c-2511.91,413.09) R8E.1@-2475,413.09 ; -2511.91,450 cw(c-2511.91,413.09) R8E.1@-2475,413.09 ; -2511.91,450 cw(c-2511.91,413.09) R8E.1@-2475,413.09
  Int5 (ST) w6: v1(-2825,362.5) ccw(c-2800,362.5) -2800,337.5 -2700,337.5 cw(c-2700,312.5) -2675,312.5 ccw(c-2650,312.5) -2650,287.5 ; v1(-1737.5,100) -1741.16,103.66 ccw(c-1762.5,82.32) -1762.5,112.5 -1858.58,112.5 cw(c-1858.58,212.5) -1929.29,141.79 -2062.5,275 ccw(c-2092.68,244.82) -2092.68,287.5 ; -2650,287.5 -2092.68,287.5 ; -2650,287.5 -2092.68,287.5
  Bottom Layer w9: v1(-2825,362.5) R447E.1@-2750,362.5
D6C_N: C399I.2 R7I.1 R399I.1 U3I.6 U35C.36 | length 3167.2
  Top Layer w9: U3I.6@-2563.78,-587.5 v1(-2525,-587.5) -2475.59,-587.5 R7I.1@-2475,-586.91 ; v1(-1737.5,-775) ccw(c-1732.5,-775) -1732.5,-780 -1725,-780 ccw(c-1725,-743.58) -1688.58,-743.58 U35C.36@-1688.58,-677.5
  Int6 (SB) w6: v1(-2525,-587.5) ccw(c-2585.36,-647.86) -2585.36,-562.5 -2650,-562.5 ccw(c-2650,-587.5) -2650,-612.5 ; v1(-1737.5,-775) cw(c-1767.68,-744.82) -1767.5,-787.5 ; -2650,-612.5 -2092.68,-612.5 ; -2650,-612.5 -2092.68,-612.5 ; -2650,-612.5 -2092.68,-612.5 ; -2650,-612.5 -2092.68,-612.5 ; -2092.68,-612.5 cw(c-2092.68,-655.18) -2062.5,-625 -1929.29,-758.21 ccw(c-1858.58,-687.5) -1858.58,-787.5 -1767.68,-787.5 ; -1767.68,-787.5 ccw(c-1767.68,-744.82) -1767.5,-787.5 ; -1767.68,-787.5 -1767.5,-787.5
  Bottom Layer w9: R399I.1@-2600,-587.5 v1(-2525,-587.5)
D6C_P: C463I.2 R8I.1 R447I.1 U3I.2 U35C.37 | length 2750.2
  Top Layer w9: U3I.2@-2786.22,-537.5 v1(-2825,-537.5) cw(c-2825,-512.5) -2850,-512.5 -2850,-487.5 cw(c-2812.5,-487.5) -2812.5,-450 -2511.91,-450 ; v1(-1737.5,-800) cw(c-1732.5,-800) -1732.5,-795 -1725,-795 ccw(c-1725,-738.9) -1668.9,-738.9 U35C.37@-1668.9,-677.5 ; -2511.91,-450 cw(c-2511.91,-486.91) R8I.1@-2475,-486.91 ; -2511.91,-450 cw(c-2511.91,-486.91) R8I.1@-2475,-486.91 ; -2511.91,-450 cw(c-2511.91,-486.91) R8I.1@-2475,-486.91 ; -2511.91,-450 cw(c-2511.91,-486.91) R8I.1@-2475,-486.91 ; -2511.91,-450 cw(c-2511.91,-486.91) R8I.1@-2475,-486.91
  Int5 (ST) w6: v1(-2825,-537.5) ccw(c-2800,-537.5) -2800,-562.5 -2700,-562.5 cw(c-2700,-587.5) -2675,-587.5 ccw(c-2650,-587.5) -2650,-612.5 ; v1(-1737.5,-800) -1741.16,-796.34 ccw(c-1762.5,-817.68) -1762.5,-787.5 -1858.58,-787.5 cw(c-1858.58,-687.5) -1929.29,-758.21 -2062.5,-625 ccw(c-2092.68,-655.18) -2092.68,-612.5 ; -2650,-612.5 -2092.68,-612.5 ; -2650,-612.5 -2092.68,-612.5
  Bottom Layer w9: v1(-2825,-537.5) R447I.1@-2750,-537.5
D6D_N: C399M.2 R7M.1 R399M.1 U3M.6 U35D.36 | length 2609.9
  Top Layer w9: U3M.6@-2563.78,-1487.5 v1(-2525,-1487.5) -2475.59,-1487.5 R7M.1@-2475,-1486.91 ; v1(-1737.5,-1675) ccw(c-1732.5,-1675) -1732.5,-1680 -1725,-1680 ccw(c-1725,-1643.58) -1688.58,-1643.58 U35D.36@-1688.58,-1577.5
  Int6 (SB) w6: v1(-2525,-1487.5) ccw(c-2585.36,-1547.86) -2585.36,-1462.5 -2650,-1462.5 ccw(c-2650,-1487.5) -2675,-1487.5 ccw(c-2650,-1487.5) -2650,-1512.5 ; v1(-1737.5,-1675) cw(c-1767.68,-1644.82) -1767.5,-1687.5 ; -2650,-1512.5 -2092.68,-1512.5 ; -2650,-1512.5 -2092.68,-1512.5 ; -2650,-1512.5 -2092.68,-1512.5 ; -2092.68,-1512.5 cw(c-2092.68,-1555.18) -2062.5,-1525 -1929.29,-1658.21 ccw(c-1858.58,-1587.5) -1858.58,-1687.5 -1767.68,-1687.5 ; -1767.68,-1687.5 ccw(c-1767.68,-1644.82) -1767.5,-1687.5 ; -1767.68,-1687.5 -1767.5,-1687.5
  Bottom Layer w9: R399M.1@-2600,-1487.5 v1(-2525,-1487.5)
D6D_P: C463M.2 R8M.1 R447M.1 U3M.2 U35D.37 | length 2192.8
  Top Layer w9: U3M.2@-2786.22,-1437.5 v1(-2825,-1437.5) cw(c-2825,-1412.5) -2850,-1412.5 -2850,-1387.5 cw(c-2812.5,-1387.5) -2812.5,-1350 -2511.91,-1350 ; v1(-1737.5,-1700) cw(c-1732.5,-1700) -1732.5,-1695 -1725,-1695 ccw(c-1725,-1638.9) -1668.9,-1638.9 U35D.37@-1668.9,-1577.5 ; -2511.91,-1350 cw(c-2511.91,-1386.91) R8M.1@-2475,-1386.91 ; -2511.91,-1350 cw(c-2511.91,-1386.91) R8M.1@-2475,-1386.91 ; -2511.91,-1350 cw(c-2511.91,-1386.91) R8M.1@-2475,-1386.91 ; -2511.91,-1350 cw(c-2511.91,-1386.91) R8M.1@-2475,-1386.91 ; -2511.91,-1350 cw(c-2511.91,-1386.91) R8M.1@-2475,-1386.91
  Int5 (ST) w6: v1(-2825,-1437.5) ccw(c-2800,-1437.5) -2800,-1462.5 -2700,-1462.5 cw(c-2700,-1487.5) -2675,-1487.5 ccw(c-2650,-1487.5) -2650,-1512.5 -2092.68,-1512.5 cw(c-2092.68,-1555.18) -2062.5,-1525 -1929.29,-1658.21 ccw(c-1858.58,-1587.5) -1858.58,-1687.5 -1762.5,-1687.5 cw(c-1762.5,-1717.68) -1741.16,-1696.34 v1(-1737.5,-1700)
  Bottom Layer w9: v1(-2825,-1437.5) R447M.1@-2750,-1437.5
D7A_N: C399B.2 R7B.1 R399B.1 U3B.6 U35A.14 | length 2037.1
  Top Layer w9: U3B.6@-2563.78,1437.5 v1(-2525,1437.5) -2475.59,1437.5 R7B.1@-2475,1438.09 ; v1(-1762.5,1662.5) ccw(c-1757.5,1662.5) -1757.5,1657.5 -1747.5,1657.5 cw(c-1747.5,1618.27) -1708.27,1618.27 U35A.14@-1708.27,1577.5
  Int6 (SB) w6: v1(-2525,1437.5) ccw(c-2585.36,1377.14) -2585.36,1462.5 -2650,1462.5 ccw(c-2650,1437.5) -2650,1412.5 ; v1@-1762.86,1662.75 cw(c-1787.5,1680.18) -1787.5,1650 -1812.5,1650 ccw(c-1812.5,1589.64) -1855.18,1632.32 -2062.5,1425 cw(c-2092.68,1455.18) -2092.68,1412.5 ; -2650,1412.5 -2092.68,1412.5 ; -2650,1412.5 -2092.68,1412.5
  Bottom Layer w9: R399B.1@-2600,1437.5 v1(-2525,1437.5)
D7A_P: C463B.2 R8B.1 R447B.1 U3B.2 U35A.15 | length 2124
  Top Layer w9: U3B.2@-2786.22,1487.5 v1(-2825,1487.5) cw(c-2825,1512.5) -2850,1512.5 -2850,1537.5 cw(c-2812.5,1537.5) -2812.5,1575 -2511.91,1575 ; v1(-1762.5,1637.5) cw(c-1757.5,1637.5) -1757.5,1642.5 -1747.5,1642.5 cw(c-1747.5,1622.95) -1727.95,1622.95 U35A.15@-1727.95,1577.5 ; -2511.91,1575 cw(c-2511.91,1538.09) R8B.1@-2475,1538.09 ; -2511.91,1575 cw(c-2511.91,1538.09) R8B.1@-2475,1538.09 ; -2511.91,1575 cw(c-2511.91,1538.09) R8B.1@-2475,1538.09 ; -2511.91,1575 cw(c-2511.91,1538.09) R8B.1@-2475,1538.09 ; -2511.91,1575 cw(c-2511.91,1538.09) R8B.1@-2475,1538.09
  Int5 (ST) w6: v1(-2825,1487.5) ccw(c-2800,1487.5) -2800,1462.5 -2700,1462.5 cw(c-2700,1437.5) -2675,1437.5 ccw(c-2650,1437.5) -2650,1412.5 -2092.68,1412.5 ccw(c-2092.68,1455.18) -2062.5,1425 -1855.18,1632.32 cw(c-1812.5,1589.64) -1812.5,1650 -1792.68,1650 cw(c-1792.68,1607.32) v1(-1762.5,1637.5)
  Bottom Layer w9: v1(-2825,1487.5) R447B.1@-2750,1487.5
D7B_N: C399F.2 R7F.1 R399F.1 U3F.6 U35B.14 | length 3151.7
  Top Layer w9: U3F.6@-2563.78,537.5 v1(-2525,537.5) -2475.59,537.5 R7F.1@-2475,538.09 ; v1(-1762.5,762.5) ccw(c-1757.5,762.5) -1757.5,757.5 -1747.5,757.5 cw(c-1747.5,718.27) -1708.27,718.27 U35B.14@-1708.27,677.5
  Int6 (SB) w6: v1(-2525,537.5) ccw(c-2585.36,477.14) -2585.36,562.5 -2650,562.5 ccw(c-2650,537.5) -2650,512.5 ; v1@-1762.86,762.75 cw(c-1787.5,780.18) -1787.5,750 -1812.5,750 ccw(c-1812.5,689.64) -1855.18,732.32 -2062.5,525 cw(c-2092.68,555.18) -2092.68,512.5 ; -2650,512.5 -2092.68,512.5 ; -2650,512.5 -2092.68,512.5 ; -2650,512.5 -2092.68,512.5 ; -2650,512.5 -2092.68,512.5
  Bottom Layer w9: R399F.1@-2600,537.5 v1(-2525,537.5)
D7B_P: C463F.2 R8F.1 R447F.1 U3F.2 U35B.15 | length 2681.4
  Top Layer w9: U3F.2@-2786.22,587.5 v1(-2825,587.5) cw(c-2825,612.5) -2850,612.5 -2850,637.5 cw(c-2812.5,637.5) -2812.5,675 -2511.91,675 ; v1(-1762.5,737.5) cw(c-1757.5,737.5) -1757.5,742.5 -1747.5,742.5 cw(c-1747.5,722.95) -1727.95,722.95 U35B.15@-1727.95,677.5 ; -2511.91,675 cw(c-2511.91,638.09) R8F.1@-2475,638.09 ; -2511.91,675 cw(c-2511.91,638.09) R8F.1@-2475,638.09 ; -2511.91,675 cw(c-2511.91,638.09) R8F.1@-2475,638.09 ; -2511.91,675 cw(c-2511.91,638.09) R8F.1@-2475,638.09 ; -2511.91,675 cw(c-2511.91,638.09) R8F.1@-2475,638.09
  Int5 (ST) w6: v1(-2825,587.5) ccw(c-2800,587.5) -2800,562.5 -2700,562.5 cw(c-2700,537.5) -2675,537.5 ccw(c-2650,537.5) -2650,512.5 ; v1(-1762.5,737.5) ccw(c-1792.68,707.32) -1792.68,750 -1812.5,750 ccw(c-1812.5,689.64) -1855.18,732.32 -2062.5,525 cw(c-2092.68,555.18) -2092.68,512.5 ; -2650,512.5 -2092.68,512.5 ; -2650,512.5 -2092.68,512.5
  Bottom Layer w9: v1(-2825,587.5) R447F.1@-2750,587.5
D7C_N: C399J.2 R7J.1 R399J.1 U3J.6 U35C.14 | length 3151.7
  Top Layer w9: U3J.6@-2563.78,-362.5 v1(-2525,-362.5) -2475.59,-362.5 R7J.1@-2475,-361.91 ; v1(-1762.5,-137.5) ccw(c-1757.5,-137.5) -1757.5,-142.5 -1747.5,-142.5 cw(c-1747.5,-181.73) -1708.27,-181.73 U35C.14@-1708.27,-222.5
  Int6 (SB) w6: v1(-2525,-362.5) ccw(c-2585.36,-422.86) -2585.36,-337.5 -2650,-337.5 ccw(c-2650,-362.5) -2650,-387.5 ; v1@-1762.86,-137.25 cw(c-1787.5,-119.82) -1787.5,-150 -1812.5,-150 ccw(c-1812.5,-210.36) -1855.18,-167.68 -2062.5,-375 cw(c-2092.68,-344.82) -2092.68,-387.5 ; -2650,-387.5 -2092.68,-387.5 ; -2650,-387.5 -2092.68,-387.5 ; -2650,-387.5 -2092.68,-387.5 ; -2650,-387.5 -2092.68,-387.5
  Bottom Layer w9: R399J.1@-2600,-362.5 v1(-2525,-362.5)
D7C_P: C463J.2 R8J.1 R447J.1 U3J.2 U35C.15 | length 2681.4
  Top Layer w9: U3J.2@-2786.22,-312.5 v1(-2825,-312.5) cw(c-2825,-287.5) -2850,-287.5 -2850,-262.5 cw(c-2812.5,-262.5) -2812.5,-225 -2511.91,-225 ; v1(-1762.5,-162.5) cw(c-1757.5,-162.5) -1757.5,-157.5 -1747.5,-157.5 cw(c-1747.5,-177.05) -1727.95,-177.05 U35C.15@-1727.95,-222.5 ; -2511.91,-225 cw(c-2511.91,-261.91) R8J.1@-2475,-261.91 ; -2511.91,-225 cw(c-2511.91,-261.91) R8J.1@-2475,-261.91 ; -2511.91,-225 cw(c-2511.91,-261.91) R8J.1@-2475,-261.91 ; -2511.91,-225 cw(c-2511.91,-261.91) R8J.1@-2475,-261.91 ; -2511.91,-225 cw(c-2511.91,-261.91) R8J.1@-2475,-261.91
  Int5 (ST) w6: v1(-2825,-312.5) ccw(c-2800,-312.5) -2800,-337.5 -2700,-337.5 cw(c-2700,-362.5) -2675,-362.5 ccw(c-2650,-362.5) -2650,-387.5 ; v1(-1762.5,-162.5) ccw(c-1792.68,-192.68) -1792.68,-150 -1812.5,-150 ccw(c-1812.5,-210.36) -1855.18,-167.68 -2062.5,-375 cw(c-2092.68,-344.82) -2092.68,-387.5 ; -2650,-387.5 -2092.68,-387.5 ; -2650,-387.5 -2092.68,-387.5
  Bottom Layer w9: v1(-2825,-312.5) R447J.1@-2750,-312.5
D7D_N: C399N.2 R7N.1 R399N.1 U3N.6 U35D.14 | length 2594.4
  Top Layer w9: U3N.6@-2563.78,-1262.5 v1(-2525,-1262.5) -2475.59,-1262.5 R7N.1@-2475,-1261.91 ; v1(-1762.5,-1037.5) ccw(c-1757.5,-1037.5) -1757.5,-1042.5 -1747.5,-1042.5 cw(c-1747.5,-1081.73) -1708.27,-1081.73 U35D.14@-1708.27,-1122.5
  Int6 (SB) w6: v1(-2525,-1262.5) ccw(c-2585.36,-1322.86) -2585.36,-1237.5 -2650,-1237.5 ccw(c-2650,-1262.5) -2675,-1262.5 ccw(c-2650,-1262.5) -2650,-1287.5 ; v1@-1762.86,-1037.25 cw(c-1787.5,-1019.82) -1787.5,-1050 -1812.5,-1050 ccw(c-1812.5,-1110.36) -1855.18,-1067.68 -2062.5,-1275 cw(c-2092.68,-1244.82) -2092.68,-1287.5 ; -2650,-1287.5 -2092.68,-1287.5 ; -2650,-1287.5 -2092.68,-1287.5 ; -2650,-1287.5 -2092.68,-1287.5
  Bottom Layer w9: R399N.1@-2600,-1262.5 v1(-2525,-1262.5)
D7D_P: C463N.2 R8N.1 R447N.1 U3N.2 U35D.15 | length 2681.4
  Top Layer w9: U3N.2@-2786.22,-1212.5 v1(-2825,-1212.5) cw(c-2825,-1187.5) -2850,-1187.5 -2850,-1162.5 cw(c-2812.5,-1162.5) -2812.5,-1125 -2511.91,-1125 ; v1(-1762.5,-1062.5) cw(c-1757.5,-1062.5) -1757.5,-1057.5 -1747.5,-1057.5 cw(c-1747.5,-1077.05) -1727.95,-1077.05 U35D.15@-1727.95,-1122.5 ; -2511.91,-1125 cw(c-2511.91,-1161.91) R8N.1@-2475,-1161.91 ; -2511.91,-1125 cw(c-2511.91,-1161.91) R8N.1@-2475,-1161.91 ; -2511.91,-1125 cw(c-2511.91,-1161.91) R8N.1@-2475,-1161.91 ; -2511.91,-1125 cw(c-2511.91,-1161.91) R8N.1@-2475,-1161.91 ; -2511.91,-1125 cw(c-2511.91,-1161.91) R8N.1@-2475,-1161.91
  Int5 (ST) w6: v1(-2825,-1212.5) ccw(c-2800,-1212.5) -2800,-1237.5 -2700,-1237.5 cw(c-2700,-1262.5) -2675,-1262.5 ccw(c-2650,-1262.5) -2650,-1287.5 ; v1(-1762.5,-1062.5) ccw(c-1792.68,-1092.68) -1792.68,-1050 -1812.5,-1050 ccw(c-1812.5,-1110.36) -1855.18,-1067.68 -2062.5,-1275 cw(c-2092.68,-1244.82) -2092.68,-1287.5 ; -2650,-1287.5 -2092.68,-1287.5 ; -2650,-1287.5 -2092.68,-1287.5
  Bottom Layer w9: v1(-2825,-1212.5) R447N.1@-2750,-1212.5
D8A_N: C319A.2 R7A.2 R335A.1 U19A.6 U35A.35 | length 2373.6
  Top Layer w9: U19A.6@-2163.78,1212.5 v1(-2125,1212.5) ; v1(-1762.5,1037.5) cw(c-1757.5,1037.5) -1757.5,1042.5 -1747.5,1042.5 ccw(c-1747.5,1081.73) -1708.27,1081.73 U35A.35@-1708.27,1122.5 ; R7A.2@-2475,1161.91 ccw(c-2438.09,1161.91) -2438.09,1125 ; R7A.2@-2475,1161.91 ccw(c-2438.09,1161.91) -2438.09,1125 ; R7A.2@-2475,1161.91 ccw(c-2438.09,1161.91) -2438.09,1125 ; R7A.2@-2475,1161.91 ccw(c-2438.09,1161.91) -2438.09,1125 ; R7A.2@-2475,1161.91 ccw(c-2438.09,1161.91) -2438.09,1125 ; -2438.09,1125 -2125,1125 ; -2125,1125 ccw(c-2125,1150) -2100,1150 ; -2125,1125 ccw(c-2125,1150) -2100,1150 ; -2125,1125 ccw(c-2125,1150) -2100,1150 ; -2125,1125 ccw(c-2125,1150) -2100,1150 ; -2125,1125 ccw(c-2125,1150) -2100,1150 ; -2125,1125 ccw(c-2125,1150) -2100,1150 ; -2125,1125 ccw(c-2125,1150) -2100,1150 ; -2125,1125 ccw(c-2125,1150) -2100,1150 ; -2125,1125 ccw(c-2125,1150) -2100,1150 ; -2125,1125 ccw(c-2125,1150) -2100,1150 ; -2125,1125 ccw(c-2125,1150) -2100,1150 ; v1(-2125,1212.5) cw(c-2125,1187.5) -2100,1187.5 ; v1(-2125,1212.5) cw(c-2125,1187.5) -2100,1187.5 ; v1(-2125,1212.5) cw(c-2125,1187.5) -2100,1187.5 ; v1(-2125,1212.5) cw(c-2125,1187.5) -2100,1187.5 ; v1(-2125,1212.5) cw(c-2125,1187.5) -2100,1187.5 ; v1(-2125,1212.5) cw(c-2125,1187.5) -2100,1187.5 ; -2100,1150 -2100,1187.5 ; -2100,1150 -2100,1187.5
  Int6 (SB) w6: v1(-2125,1212.5) ccw(c-2185.36,1152.14) -2185.36,1237.5 -2250,1237.5 cw(c-2250,1262.5) -2275,1262.5 cw(c-2250,1262.5) -2250,1287.5 -2100,1287.5 cw(c-2100,1257.32) -2078.66,1278.66 -1879.29,1079.29 ccw(c-1808.58,1150) -1808.58,1050 -1792.68,1050 ; -1792.5,1050 -1792.68,1050 ; v1(-1762.5,1037.5) ccw(c-1792.68,1007.32) -1792.68,1050
  Bottom Layer w9: R335A.1@-2200,1212.5 v1(-2125,1212.5)
D8A_P: C383A.2 R8A.2 R383A.1 U19A.2 U35A.34 | length 1358.4
  Top Layer w9: R8A.2@-2475,1261.91 v1(-2425,1262.5) U19A.2@-2386.22,1262.5 U19A.2@-2380,1262.5 ; v1(-1762.5,1062.5) ccw(c-1757.5,1062.5) -1757.5,1057.5 -1747.5,1057.5 ccw(c-1747.5,1077.05) -1727.95,1077.05 U35A.34@-1727.95,1122.5
  Int5 (ST) w6: v1(-2425,1262.5) ccw(c-2364.64,1322.86) -2364.64,1237.5 -2300,1237.5 ccw(c-2300,1262.5) -2275,1262.5 cw(c-2250,1262.5) -2250,1287.5 ; v1(-1762.5,1062.5) -1766.16,1058.84 cw(c-1787.5,1080.18) -1787.5,1050 -1808.58,1050 cw(c-1808.58,1150) -1879.29,1079.29 -2078.66,1278.66 ccw(c-2100,1257.32) -2100,1287.5 ; -2250,1287.5 -2100,1287.5 ; -2250,1287.5 -2100,1287.5 ; -2250,1287.5 -2100,1287.5
  Bottom Layer w9: v1(-2425,1262.5) R383A.1@-2350,1262.5
D8B_N: C319E.2 R7E.2 R335E.1 U19E.6 U35B.35 | length 3191.2
  Top Layer w9: U19E.6@-2163.78,312.5 v1(-2125,312.5) ; v1(-1762.5,137.5) cw(c-1757.5,137.5) -1757.5,142.5 -1747.5,142.5 ccw(c-1747.5,181.73) -1708.27,181.73 U35B.35@-1708.27,222.5 ; R7E.2@-2475,261.91 ccw(c-2438.09,261.91) -2438.09,225 ; R7E.2@-2475,261.91 ccw(c-2438.09,261.91) -2438.09,225 ; R7E.2@-2475,261.91 ccw(c-2438.09,261.91) -2438.09,225 ; R7E.2@-2475,261.91 ccw(c-2438.09,261.91) -2438.09,225 ; R7E.2@-2475,261.91 ccw(c-2438.09,261.91) -2438.09,225 ; -2438.09,225 -2125,225 ; -2125,225 ccw(c-2125,250) -2100,250 ; -2125,225 ccw(c-2125,250) -2100,250 ; -2125,225 ccw(c-2125,250) -2100,250 ; -2125,225 ccw(c-2125,250) -2100,250 ; -2125,225 ccw(c-2125,250) -2100,250 ; -2125,225 ccw(c-2125,250) -2100,250 ; -2125,225 ccw(c-2125,250) -2100,250 ; -2125,225 ccw(c-2125,250) -2100,250 ; -2125,225 ccw(c-2125,250) -2100,250 ; -2125,225 ccw(c-2125,250) -2100,250 ; -2125,225 ccw(c-2125,250) -2100,250 ; -2125,225 ccw(c-2125,250) -2100,250 ; -2125,225 ccw(c-2125,250) -2100,250 ; -2125,225 ccw(c-2125,250) -2100,250 ; -2125,225 ccw(c-2125,250) -2100,250 ; -2125,225 ccw(c-2125,250) -2100,250 ; -2125,225 ccw(c-2125,250) -2100,250 ; -2125,225 ccw(c-2125,250) -2100,250 ; -2125,225 ccw(c-2125,250) -2100,250 ; -2125,225 ccw(c-2125,250) -2100,250 ; -2125,225 ccw(c-2125,250) -2100,250 ; -2125,225 ccw(c-2125,250) -2100,250 ; v1(-2125,312.5) cw(c-2125,287.5) -2100,287.5 ; v1(-2125,312.5) cw(c-2125,287.5) -2100,287.5 ; v1(-2125,312.5) cw(c-2125,287.5) -2100,287.5 ; v1(-2125,312.5) cw(c-2125,287.5) -2100,287.5 ; v1(-2125,312.5) cw(c-2125,287.5) -2100,287.5 ; v1(-2125,312.5) cw(c-2125,287.5) -2100,287.5 ; v1(-2125,312.5) cw(c-2125,287.5) -2100,287.5 ; v1(-2125,312.5) cw(c-2125,287.5) -2100,287.5 ; v1(-2125,312.5) cw(c-2125,287.5) -2100,287.5 ; v1(-2125,312.5) cw(c-2125,287.5) -2100,287.5 ; v1(-2125,312.5) cw(c-2125,287.5) -2100,287.5 ; v1(-2125,312.5) cw(c-2125,287.5) -2100,287.5 ; -2100,250 -2100,287.5 ; -2100,250 -2100,287.5
  Int6 (SB) w6: v1(-2125,312.5) ccw(c-2185.36,252.14) -2185.36,337.5 -2250,337.5 cw(c-2250,362.5) -2275,362.5 cw(c-2250,362.5) -2250,387.5 ; -1792.5,150 -1792.68,150 ; v1(-1762.5,137.5) ccw(c-1792.68,107.32) -1792.68,150 ; -2250,387.5 -2100,387.5 ; -2250,387.5 -2100,387.5 ; -2100,387.5 cw(c-2100,357.32) -2078.66,378.66 -1879.29,179.29 ccw(c-1808.58,250) -1808.58,150 -1792.68,150
  Bottom Layer w9: R335E.1@-2200,312.5 v1(-2125,312.5)
D8B_P: C383E.2 R8E.2 R383E.1 U19E.2 U35B.34 | length 1808.4
  Top Layer w9: R8E.2@-2475,361.91 v1(-2425,362.5) U19E.2@-2386.22,362.5 U19E.2@-2380,362.5 ; v1(-1762.5,162.5) ccw(c-1757.5,162.5) -1757.5,157.5 -1747.5,157.5 ccw(c-1747.5,177.05) -1727.95,177.05 U35B.34@-1727.95,222.5
  Int5 (ST) w6: v1(-2425,362.5) ccw(c-2364.64,422.86) -2364.64,337.5 -2300,337.5 ccw(c-2300,362.5) -2275,362.5 cw(c-2250,362.5) -2250,387.5 ; v1(-1762.5,162.5) -1766.16,158.84 cw(c-1787.5,180.18) -1787.5,150 -1808.58,150 cw(c-1808.58,250) -1879.29,179.29 -2078.66,378.66 ccw(c-2100,357.32) -2100,387.5 ; -2250,387.5 -2100,387.5 ; -2250,387.5 -2100,387.5 ; -2250,387.5 -2100,387.5 ; -2250,387.5 -2100,387.5 ; -2250,387.5 -2100,387.5 ; -2250,387.5 -2100,387.5
  Bottom Layer w9: v1(-2425,362.5) R383E.1@-2350,362.5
